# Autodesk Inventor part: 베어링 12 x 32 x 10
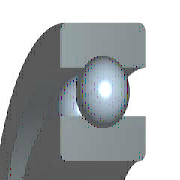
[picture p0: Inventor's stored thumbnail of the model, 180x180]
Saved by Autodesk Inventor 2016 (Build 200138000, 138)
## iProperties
IsCustomPart: 1
Created: 2012-02
Part Number: 베어링 12 x 32 x 10
Material: 강철, 연강
Description: 깊은 그루브 볼 베어링
Document SubType Name: Modeling
Standard: KS B 2023
Designer: test
Standards Organization: KS
Language: ko-KR
Size Designation: 6201 - 12 x 32 x 10
Categories: <MemberInstance><Categories><Category DisplayName="샤프트 부품" InternalName="7f7aeb1f-a693-4053-b835-cee3144e0d98" Mnemonic="SHFT"><Category DisplayName="베어링" Inter
Density: 1 g/cm^3
Appearance: 노란색
Author: test
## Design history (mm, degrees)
sketch "스케치" dims "d0" = 5.2 (= -0.26 x WD + 0.26 x BD)
  geometry: L1 (2.4, 11)-(7.6, 11); L2 (5, 11)-(5, 8.4); L3 (5, 11)-(5, 13.6); L4 (3.068, 9.26)-(0, 9.26); L5 (0, 6)-(10, 6); L6 (3.068, 12.74)-(0, 12.74); L7 (0, 16)-(10, 16); L8 (10, 6)-(10, 9.26); L9 (6.932, 9.26)-(10, 9.26); L10 (6.932, 12.74)-(10, 12.74); L11 (10, 16)-(10, 12.74); L12 (-1.4, 0)-(8.4, 0) reference; L13 (0, -0.3)-(0, 5.3) reference
  constraints: 22 end point, 4 point on line, 2 collinear, 2 perpendicular, 2 symmetric about line, 1 midpoint, 1 parallel, 14 other
  dimensions: "d9" = 12 diameter of L5 L12 (= WD); "d11" = 32 diameter of L7 L12 (= BD); "d12" = 10 distance between parallel lines of L8 L13 (= KB); "d13" = 18.52 diameter of L9 L12 (= 0.326 x BD + 0.674 x WD)
revolve "본체" stored, may be unused: angle "d6" = 90 deg
revolve "볼" stored, may be unused: angle "d7" = 90 deg
pattern_circular "IDS_ARRAYBALL[SIMPL:T]" dims angle "d3" = 360 deg
body "Solid1"
fillet "모깎기1" dims "d1" = 0.6 (= KRS)
other parameters: "WD" = 12 [user parameter; used in 5 equation terms], "BD" = 32 [user parameter; used in 5 equation terms], "KB" = 10 [user parameter; used in 1 equation term], "KRS" = 0.6 [user parameter; used in 1 equation term], "d4" = 0, "d5" = 0, "d8" = 0, "d14" = 0, "d15" = 0, "BBA" = 0 [user parameter], "BC0" = 3100000 [user parameter], "BC" = 6890000 [user parameter], "BR" = 16 (= 0.5 x BD) [user parameter], "WR" = 6 (= 0.5 x WD) [user parameter]
